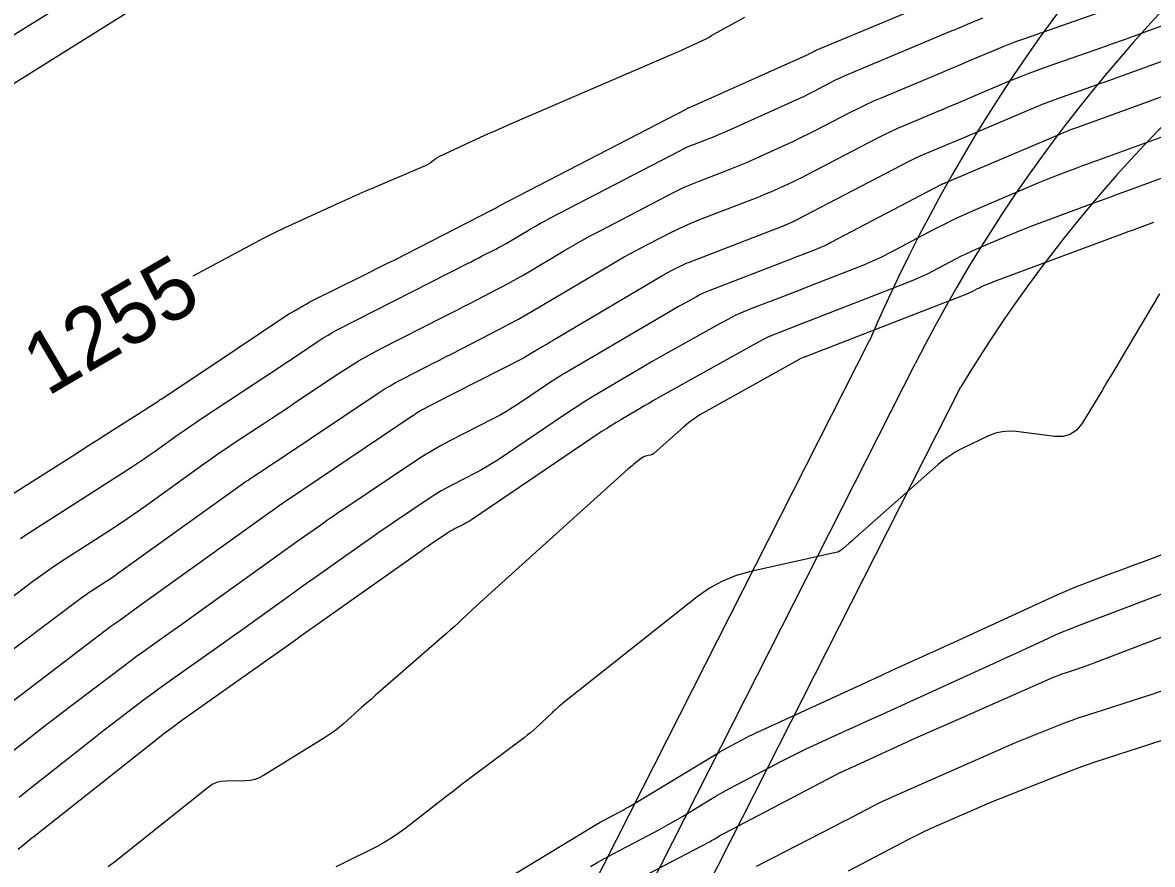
# Model space of a CAD drawing. Extents: x 658976 to 668721, y 639543 to 647196.
# Drawn here: x 662250.4 to 662361, y 642066.5 to 642148.9 of the extents above; entities that cross this region are included whole.
import ezdxf

# ---------------------------------------------------------------- set-up
doc = ezdxf.new("R2010")
doc.units = 0
for name, color, linetype in [('Ex_Contour Labels', 7, 'Continuous'), ('Ex_Major Contours', 7, 'Continuous'), ('Ex_Minor Contours', 7, 'Continuous'), ('R_Water', 7, 'Continuous')]:
    doc.layers.add(name, color=color, linetype=linetype)

msp = doc.modelspace()

# ---------------------------------------------------------------- linework, layer by layer
at = {"layer": 'Ex_Major Contours'}
for points in [[(662260.86, 642150.06), (662245.33, 642140.36)], [(662267.07, 642124.14), (662273.12, 642127.37), (662274.1, 642127.89), (662275.08, 642128.38), (662276.08, 642128.86), (662277.08, 642129.33), (662281.38, 642131.28), (662282.24, 642131.68), (662283.11, 642132.06), (662283.98, 642132.44), (662284.85, 642132.81), (662289.84, 642134.94), (662289.97, 642135), (662290.09, 642135.06), (662290.2, 642135.14), (662290.31, 642135.22), (662290.75, 642135.55), (662290.86, 642135.63), (662290.98, 642135.71), (662291.1, 642135.78), (662291.22, 642135.84), (662295.22, 642137.7), (662295.93, 642138.02), (662296.64, 642138.34), (662297.35, 642138.66), (662298.07, 642138.97), (662314.38, 642146), (662314.69, 642146.13), (662315, 642146.27), (662315.31, 642146.41), (662315.62, 642146.56), (662317.36, 642147.37), (662317.42, 642147.4), (662317.48, 642147.43), (662317.54, 642147.47), (662317.6, 642147.5), (662317.82, 642147.66), (662317.87, 642147.7), (662317.93, 642147.74), (662317.99, 642147.77), (662318.05, 642147.81), (662321.09, 642149.47)], [(662366.24, 642146.7), (662357.08, 642143.37), (662356.45, 642143.14), (662355.83, 642142.92), (662355.2, 642142.7), (662354.58, 642142.48), (662352.07, 642141.6), (662351.45, 642141.38), (662350.83, 642141.15), (662350.21, 642140.9), (662349.6, 642140.65), (662341.54, 642137.23), (662341.17, 642137.08), (662340.81, 642136.93), (662340.44, 642136.77), (662340.08, 642136.62), (662338.61, 642136), (662338.24, 642135.85), (662337.88, 642135.68), (662337.53, 642135.51), (662337.17, 642135.33), (662326.11, 642129.57), (662326, 642129.51), (662325.89, 642129.45), (662325.78, 642129.4), (662325.67, 642129.35), (662325.21, 642129.14), (662325.1, 642129.09), (662324.98, 642129.05), (662324.87, 642129), (662324.75, 642128.95), (662315.53, 642125.41), (662315.31, 642125.32), (662315.09, 642125.22), (662314.87, 642125.12), (662314.66, 642125.02), (662313.81, 642124.58), (662313.6, 642124.46), (662313.39, 642124.35), (662313.18, 642124.23), (662312.98, 642124.11), (662302.27, 642117.77), (662302.03, 642117.62), (662301.79, 642117.48), (662301.55, 642117.34), (662301.31, 642117.2), (662299.93, 642116.39), (662299.9, 642116.37), (662299.86, 642116.34), (662299.82, 642116.32), (662299.78, 642116.3), (662299.64, 642116.2), (662299.6, 642116.17), (662299.56, 642116.15), (662299.53, 642116.13), (662299.49, 642116.11), (662292.59, 642112.59), (662292.27, 642112.43), (662291.96, 642112.27), (662291.65, 642112.11), (662291.34, 642111.95), (662289.49, 642111), (662289.44, 642110.97), (662289.39, 642110.94), (662289.38, 642110.94), (662289.37, 642110.93), (662289.35, 642110.92), (662289.34, 642110.92), (662288.86, 642110.6), (662288.78, 642110.54), (662288.7, 642110.48), (662288.61, 642110.43), (662288.53, 642110.37), (662276.41, 642102.23), (662276.24, 642102.11), (662276.06, 642101.99), (662275.89, 642101.87), (662275.72, 642101.75), (662275.03, 642101.27), (662274.86, 642101.15), (662274.69, 642101.02), (662274.52, 642100.9), (662274.34, 642100.78), (662261.31, 642091.41), (662261.12, 642091.27), (662260.93, 642091.14), (662260.74, 642091), (662260.55, 642090.87), (662259.78, 642090.32), (662259.59, 642090.19), (662259.4, 642090.05), (662259.21, 642089.91), (662259.02, 642089.77), (662247.35, 642080.91)], [(662361.71, 642122.38), (662357.99, 642116.09), (662357.51, 642115.3), (662357.03, 642114.5), (662356.55, 642113.7), (662356.07, 642112.91), (662354.08, 642109.64), (662353.57, 642109.01), (662352.96, 642108.58), (662352.25, 642108.38), (662351.44, 642108.38), (662347.68, 642108.88), (662346.98, 642108.92), (662346.3, 642108.86), (662345.63, 642108.71), (662344.97, 642108.45), (662342.39, 642107.21), (662341.76, 642106.88), (662341.16, 642106.51), (662340.58, 642106.1), (662340.03, 642105.64), (662331.88, 642098.43), (662331.74, 642098.3), (662331.59, 642098.17), (662331.44, 642098.03), (662331.29, 642097.9), (662330.7, 642097.38), (662330.54, 642097.26), (662330.38, 642097.16), (662330.2, 642097.08), (662330.01, 642097.03), (662321.67, 642095.18), (662320.25, 642094.78), (662318.9, 642094.23), (662317.62, 642093.53), (662316.42, 642092.68), (662303.24, 642082.23), (662303.15, 642082.16), (662303.06, 642082.09), (662302.97, 642082.01), (662302.89, 642081.94), (662302.55, 642081.63), (662302.47, 642081.56), (662302.39, 642081.48), (662302.3, 642081.41), (662302.22, 642081.33), (662300.68, 642079.89), (662300.39, 642079.63), (662300.09, 642079.38), (662299.79, 642079.13), (662299.48, 642078.89), (662294.06, 642074.82), (662293.3, 642074.25), (662292.55, 642073.67), (662291.8, 642073.1), (662291.05, 642072.51), (662287.94, 642070.08), (662287.25, 642069.56), (662286.53, 642069.08), (662285.79, 642068.63), (662285.03, 642068.22), (662281.74, 642066.56), (662281.05, 642066.25)], [(662297.66, 642065), (662306.29, 642070.24), (662306.61, 642070.43), (662306.92, 642070.61), (662307.24, 642070.78), (662307.56, 642070.96), (662308.85, 642071.63), (662309.17, 642071.81), (662309.49, 642071.98), (662309.8, 642072.16), (662310.12, 642072.35), (662318.28, 642077.29), (662318.64, 642077.5), (662319, 642077.71), (662319.36, 642077.91), (662319.73, 642078.1), (662321.2, 642078.87), (662321.56, 642079.06), (662321.93, 642079.24), (662322.31, 642079.42), (662322.68, 642079.6), (662332.44, 642084.07), (662333.2, 642084.42), (662333.95, 642084.76), (662334.71, 642085.11), (662335.47, 642085.46), (662338.5, 642086.84), (662339.26, 642087.19), (662340.02, 642087.53), (662340.78, 642087.88), (662341.54, 642088.23), (662350.95, 642092.57), (662351.69, 642092.9), (662352.43, 642093.22), (662353.18, 642093.53), (662353.93, 642093.82), (662356.95, 642094.97), (662357.7, 642095.25), (662358.46, 642095.54), (662359.22, 642095.82), (662359.97, 642096.1), (662372.12, 642100.64)]]:
    msp.add_lwpolyline(points, dxfattribs=at)
at = {"layer": 'Ex_Minor Contours'}
for points in [[(662257.02, 642152.41), (662246.99, 642146.15)], [(662248.38, 642102.12), (662255.23, 642106.47), (662256.08, 642107.02), (662256.93, 642107.56), (662257.78, 642108.1), (662258.63, 642108.65), (662263.7, 642111.89), (662263.72, 642111.9), (662263.74, 642111.92), (662263.76, 642111.93), (662263.78, 642111.94), (662263.85, 642112), (662263.87, 642112.01), (662263.89, 642112.02), (662263.91, 642112.04), (662263.93, 642112.05), (662267.13, 642114.16), (662267.67, 642114.52), (662268.21, 642114.88), (662268.75, 642115.24), (662269.29, 642115.6), (662275.96, 642120.08), (662276.2, 642120.23), (662276.44, 642120.39), (662276.69, 642120.54), (662276.94, 642120.68), (662277.94, 642121.26), (662278.19, 642121.4), (662278.44, 642121.54), (662278.69, 642121.67), (662278.95, 642121.8), (662283.46, 642124.04), (662284.3, 642124.45), (662285.14, 642124.87), (662285.97, 642125.29), (662286.81, 642125.71), (662296.28, 642130.55), (662296.31, 642130.56), (662296.35, 642130.58), (662296.38, 642130.6), (662296.41, 642130.61), (662296.54, 642130.68), (662296.58, 642130.7), (662296.61, 642130.72), (662296.64, 642130.73), (662296.67, 642130.75), (662296.87, 642130.87), (662296.91, 642130.9), (662296.96, 642130.92), (662297, 642130.94), (662297.05, 642130.97), (662315.4, 642140.5), (662315.47, 642140.54), (662315.54, 642140.57), (662315.61, 642140.6), (662315.68, 642140.63), (662315.97, 642140.74), (662316.05, 642140.77), (662316.12, 642140.8), (662316.19, 642140.83), (662316.26, 642140.86), (662327.12, 642145.74), (662327.2, 642145.78), (662327.29, 642145.82), (662327.37, 642145.86), (662327.45, 642145.9), (662327.77, 642146.07), (662327.85, 642146.11), (662327.93, 642146.15), (662328.01, 642146.18), (662328.09, 642146.22), (662342.44, 642152.23)], [(662247.87, 642091.57), (662251.38, 642094.21), (662252.26, 642094.86), (662253.16, 642095.49), (662254.07, 642096.11), (662254.99, 642096.71), (662258.81, 642099.16), (662259.75, 642099.77), (662260.68, 642100.4), (662261.61, 642101.04), (662262.52, 642101.68), (662268.13, 642105.71), (662268.87, 642106.23), (662269.6, 642106.75), (662270.35, 642107.26), (662271.1, 642107.76), (662274.1, 642109.74), (662274.86, 642110.24), (662275.61, 642110.74), (662276.36, 642111.24), (662277.1, 642111.74), (662281.37, 642114.59), (662282.34, 642115.22), (662283.33, 642115.82), (662284.33, 642116.39), (662285.36, 642116.93), (662291.59, 642120.11), (662292.25, 642120.45), (662292.9, 642120.78), (662293.56, 642121.12), (662294.22, 642121.46), (662296.85, 642122.81), (662297.51, 642123.15), (662298.16, 642123.51), (662298.8, 642123.87), (662299.44, 642124.24), (662303.42, 642126.6), (662304.3, 642127.11), (662305.19, 642127.61), (662306.08, 642128.1), (662306.98, 642128.58), (662314.06, 642132.26), (662314.69, 642132.57), (662315.33, 642132.87), (662315.97, 642133.15), (662316.62, 642133.41), (662319.24, 642134.42), (662319.89, 642134.67), (662320.54, 642134.94), (662321.19, 642135.21), (662321.83, 642135.5), (662325.08, 642136.96), (662325.83, 642137.3), (662326.58, 642137.66), (662327.32, 642138.02), (662328.06, 642138.4), (662331.32, 642140.1), (662332.12, 642140.5), (662332.92, 642140.89), (662333.73, 642141.26), (662334.54, 642141.61), (662340.37, 642144.05), (662341.04, 642144.33), (662341.7, 642144.61), (662342.37, 642144.89), (662343.04, 642145.17), (662345.71, 642146.31), (662346.38, 642146.58), (662347.05, 642146.85), (662347.73, 642147.1), (662348.41, 642147.35), (662359.13, 642151.08)], [(662246.81, 642085.59), (662255.95, 642092.47), (662256.26, 642092.7), (662256.58, 642092.92), (662256.9, 642093.14), (662257.22, 642093.35), (662258.53, 642094.19), (662258.85, 642094.4), (662259.18, 642094.61), (662259.49, 642094.83), (662259.81, 642095.06), (662271.91, 642103.75), (662272.18, 642103.94), (662272.45, 642104.13), (662272.73, 642104.31), (662273, 642104.5), (662274.11, 642105.23), (662274.38, 642105.41), (662274.66, 642105.59), (662274.93, 642105.78), (662275.21, 642105.96), (662285.2, 642112.65), (662285.77, 642113.02), (662286.35, 642113.37), (662286.94, 642113.71), (662287.54, 642114.02), (662289.97, 642115.26), (662290.58, 642115.57), (662291.18, 642115.88), (662291.79, 642116.19), (662292.4, 642116.5), (662297.01, 642118.88), (662297.98, 642119.38), (662298.94, 642119.9), (662299.89, 642120.44), (662300.83, 642120.99), (662307.85, 642125.15), (662308.57, 642125.57), (662309.29, 642125.98), (662310.02, 642126.38), (662310.76, 642126.77), (662313.72, 642128.3), (662314.46, 642128.68), (662315.22, 642129.03), (662315.98, 642129.36), (662316.75, 642129.67), (662321.88, 642131.64), (662322.32, 642131.81), (662322.76, 642131.99), (662323.2, 642132.18), (662323.64, 642132.37), (662325.37, 642133.15), (662325.81, 642133.35), (662326.24, 642133.55), (662326.66, 642133.77), (662327.09, 642133.98), (662333.98, 642137.57), (662334.69, 642137.93), (662335.4, 642138.28), (662336.13, 642138.61), (662336.86, 642138.92), (662339.79, 642140.15), (662340.52, 642140.46), (662341.26, 642140.77), (662341.99, 642141.08), (662342.72, 642141.39), (662347.01, 642143.21), (662347.97, 642143.6), (662348.94, 642143.99), (662349.92, 642144.35), (662350.9, 642144.7), (662356.06, 642146.5), (662357.12, 642146.88), (662358.18, 642147.25), (662359.24, 642147.63), (662360.3, 642148.01), (662365.42, 642149.88)], [(662250.15, 642098.41), (662250.6, 642098.7), (662261.05, 642105.39), (662261.63, 642105.77), (662262.21, 642106.16), (662262.78, 642106.56), (662263.35, 642106.96), (662265.61, 642108.58), (662266.18, 642108.98), (662266.75, 642109.38), (662267.32, 642109.77), (662267.9, 642110.16), (662275.63, 642115.26), (662276.09, 642115.57), (662276.56, 642115.88), (662277.02, 642116.19), (662277.48, 642116.5), (662279.33, 642117.73), (662279.8, 642118.04), (662280.28, 642118.33), (662280.76, 642118.6), (662281.25, 642118.86), (662293.93, 642125.33), (662294.28, 642125.5), (662294.63, 642125.68), (662294.97, 642125.86), (662295.32, 642126.04), (662296.7, 642126.75), (662297.04, 642126.93), (662297.38, 642127.11), (662297.72, 642127.3), (662298.06, 642127.5), (662300.15, 642128.74), (662300.61, 642129), (662301.07, 642129.27), (662301.54, 642129.52), (662302.01, 642129.77), (662314.73, 642136.38), (662315.08, 642136.56), (662315.43, 642136.72), (662315.79, 642136.88), (662316.15, 642137.02), (662317.61, 642137.58), (662317.97, 642137.72), (662318.33, 642137.87), (662318.69, 642138.02), (662319.05, 642138.18), (662326.04, 642141.32), (662326.49, 642141.53), (662326.93, 642141.74), (662327.37, 642141.95), (662327.81, 642142.18), (662329.55, 642143.08), (662329.98, 642143.31), (662330.42, 642143.52), (662330.87, 642143.72), (662331.32, 642143.91), (662341.4, 642148.14), (662341.78, 642148.3), (662342.15, 642148.45), (662342.53, 642148.61), (662342.9, 642148.77), (662344.4, 642149.41)], [(662367.49, 642143.68), (662353.67, 642138.65), (662353.57, 642138.62), (662353.48, 642138.58), (662353.38, 642138.55), (662353.28, 642138.51), (662352.9, 642138.38), (662352.8, 642138.35), (662352.71, 642138.31), (662352.61, 642138.27), (662352.52, 642138.23), (662340.45, 642133.12), (662340.41, 642133.1), (662340.38, 642133.09), (662340.37, 642133.09), (662340.36, 642133.08), (662340.35, 642133.08), (662340.35, 642133.07), (662329.53, 642127.38), (662329.18, 642127.2), (662328.84, 642127.04), (662328.49, 642126.89), (662328.13, 642126.74), (662326.7, 642126.19), (662326.34, 642126.05), (662325.98, 642125.91), (662325.63, 642125.77), (662325.27, 642125.63), (662317.66, 642122.69), (662317.31, 642122.55), (662316.96, 642122.39), (662316.61, 642122.22), (662316.28, 642122.04), (662314.94, 642121.3), (662314.6, 642121.11), (662314.27, 642120.92), (662313.94, 642120.73), (662313.61, 642120.53), (662303.84, 642114.8), (662303.21, 642114.43), (662302.59, 642114.04), (662301.97, 642113.65), (662301.36, 642113.24), (662298.94, 642111.6), (662298.32, 642111.2), (662297.7, 642110.82), (662297.06, 642110.45), (662296.42, 642110.11), (662292.21, 642107.97), (662291.3, 642107.48), (662290.41, 642106.97), (662289.53, 642106.44), (662288.67, 642105.88), (662281.91, 642101.34), (662281.32, 642100.94), (662280.73, 642100.54), (662280.14, 642100.13), (662279.56, 642099.72), (662277.23, 642098.07), (662276.65, 642097.66), (662276.07, 642097.25), (662275.49, 642096.83), (662274.91, 642096.42), (662267.5, 642091.09), (662266.91, 642090.67), (662266.31, 642090.24), (662265.72, 642089.82), (662265.12, 642089.4), (662262.73, 642087.71), (662262.14, 642087.28), (662261.54, 642086.85), (662260.96, 642086.42), (662260.37, 642085.98), (662253.98, 642081.13), (662253.36, 642080.65), (662252.74, 642080.17), (662252.12, 642079.69), (662251.51, 642079.21), (662249.05, 642077.27)], [(662364.98, 642138.82), (662355.64, 642135.43), (662355.15, 642135.25), (662354.66, 642135.07), (662354.17, 642134.89), (662353.68, 642134.71), (662351.73, 642133.99), (662351.25, 642133.8), (662350.76, 642133.61), (662350.28, 642133.41), (662349.8, 642133.21), (662343.68, 642130.6), (662342.65, 642130.14), (662341.63, 642129.67), (662340.61, 642129.17), (662339.61, 642128.66), (662335.35, 642126.42), (662334.48, 642125.97), (662333.59, 642125.56), (662332.7, 642125.16), (662331.79, 642124.8), (662327.86, 642123.27), (662327.09, 642122.97), (662326.32, 642122.67), (662325.54, 642122.37), (662324.77, 642122.07), (662321.68, 642120.88), (662320.91, 642120.56), (662320.16, 642120.23), (662319.42, 642119.86), (662318.69, 642119.47), (662314.77, 642117.28), (662313.88, 642116.78), (662312.99, 642116.28), (662312.1, 642115.76), (662311.21, 642115.25), (662307.22, 642112.9), (662306.26, 642112.33), (662305.32, 642111.75), (662304.38, 642111.15), (662303.45, 642110.53), (662296.93, 642106.12), (662296.4, 642105.77), (662295.86, 642105.44), (662295.31, 642105.13), (662294.74, 642104.83), (662292.48, 642103.67), (662291.92, 642103.37), (662291.36, 642103.06), (662290.82, 642102.73), (662290.29, 642102.38), (662286.88, 642100.09), (662286.13, 642099.59), (662285.39, 642099.08), (662284.66, 642098.57), (662283.92, 642098.05), (662278.9, 642094.5), (662278.18, 642093.99), (662277.46, 642093.47), (662276.73, 642092.96), (662276.02, 642092.44), (662273.14, 642090.38), (662272.42, 642089.86), (662271.7, 642089.34), (662270.98, 642088.83), (662270.26, 642088.32), (662265.04, 642084.64), (662264.36, 642084.15), (662263.69, 642083.66), (662263.02, 642083.16), (662262.35, 642082.66), (662259.69, 642080.64), (662259.02, 642080.13), (662258.36, 642079.62), (662257.7, 642079.11), (662257.05, 642078.59), (662250.59, 642073.49), (662250.02, 642073.04)], [(662362.14, 642133.75), (662358.46, 642132.42), (662357.54, 642132.09), (662356.63, 642131.75), (662355.71, 642131.41), (662354.8, 642131.07), (662349.27, 642129.01), (662348.62, 642128.76), (662347.97, 642128.51), (662347.33, 642128.25), (662346.69, 642127.98), (662344.01, 642126.83), (662343.43, 642126.58), (662342.86, 642126.31), (662342.29, 642126.04), (662341.73, 642125.75), (662339.5, 642124.58), (662338.94, 642124.29), (662338.37, 642124.02), (662337.79, 642123.77), (662337.21, 642123.53), (662327.48, 642119.75), (662327.06, 642119.59), (662326.65, 642119.43), (662326.23, 642119.27), (662325.82, 642119.11), (662324.15, 642118.46), (662323.74, 642118.29), (662323.34, 642118.11), (662322.94, 642117.92), (662322.54, 642117.71), (662312.62, 642112.17), (662312.16, 642111.91), (662311.69, 642111.64), (662311.23, 642111.38), (662310.77, 642111.11), (662308.94, 642110.03), (662308.48, 642109.76), (662308.03, 642109.48), (662307.58, 642109.19), (662307.14, 642108.9), (662294.43, 642100.31), (662294.23, 642100.17), (662294.03, 642100.05), (662293.82, 642099.93), (662293.6, 642099.82), (662292.74, 642099.38), (662292.53, 642099.26), (662292.32, 642099.14), (662292.11, 642099.02), (662291.91, 642098.89), (662290.62, 642098.02), (662290.33, 642097.83), (662290.05, 642097.63), (662289.77, 642097.44), (662289.49, 642097.24), (662279.28, 642090.01), (662279.06, 642089.86), (662278.84, 642089.7), (662278.62, 642089.54), (662278.4, 642089.39), (662277.53, 642088.76), (662277.31, 642088.6), (662277.09, 642088.45), (662276.87, 642088.29), (662276.65, 642088.13), (662266.29, 642080.82), (662266.06, 642080.65), (662265.82, 642080.48), (662265.59, 642080.31), (662265.36, 642080.13), (662264.44, 642079.43), (662264.21, 642079.26), (662263.98, 642079.08), (662263.75, 642078.9), (662263.52, 642078.72), (662251.47, 642069.19), (662251.28, 642069.04), (662251.08, 642068.88), (662250.89, 642068.73), (662250.7, 642068.57), (662249.93, 642067.94)], [(662361.12, 642129.35), (662359.44, 642128.74), (662359.01, 642128.58), (662358.59, 642128.43), (662358.17, 642128.27), (662357.75, 642128.12), (662345.44, 642123.53), (662345.31, 642123.47), (662345.17, 642123.42), (662345.03, 642123.37), (662344.9, 642123.31), (662344.34, 642123.07), (662344.22, 642123.02), (662344.1, 642122.96), (662343.98, 642122.9), (662343.86, 642122.84), (662343.39, 642122.59), (662343.27, 642122.53), (662343.15, 642122.48), (662343.03, 642122.43), (662342.91, 642122.38), (662327.1, 642116.23), (662327.04, 642116.21), (662326.98, 642116.19), (662326.92, 642116.16), (662326.86, 642116.14), (662326.63, 642116.05), (662326.57, 642116.03), (662326.51, 642116), (662326.46, 642115.97), (662326.4, 642115.94), (662317.26, 642110.84), (662316.69, 642110.5), (662316.13, 642110.12), (662315.59, 642109.72), (662315.08, 642109.29), (662312.23, 642106.76), (662312.14, 642106.69), (662312.04, 642106.63), (662311.94, 642106.59), (662311.83, 642106.55), (662311.38, 642106.45), (662311.27, 642106.42), (662311.16, 642106.38), (662311.06, 642106.33), (662310.97, 642106.26), (662310.24, 642105.68), (662310.09, 642105.56), (662309.94, 642105.43), (662309.79, 642105.31), (662309.65, 642105.18), (662296.29, 642093.15), (662295.92, 642092.81), (662295.56, 642092.48), (662295.19, 642092.14), (662294.83, 642091.81), (662293.38, 642090.46), (662293.01, 642090.12), (662292.65, 642089.79), (662292.28, 642089.46), (662291.9, 642089.13), (662285.38, 642083.44), (662284.93, 642083.05), (662284.49, 642082.65), (662284.04, 642082.26), (662283.6, 642081.87), (662281.83, 642080.28), (662281.38, 642079.9), (662280.92, 642079.54), (662280.44, 642079.19), (662279.94, 642078.87), (662273.96, 642075.19), (662273.54, 642074.96), (662273.11, 642074.8), (662272.65, 642074.71), (662272.18, 642074.67), (662270.26, 642074.64), (662269.79, 642074.6), (662269.35, 642074.49), (662268.93, 642074.3), (662268.54, 642074.03), (662259.36, 642066.71), (662258.76, 642066.23)], [(662305.99, 642066.29), (662306.7, 642066.71), (662307.42, 642067.11), (662308.15, 642067.49), (662312.3, 642069.68), (662312.98, 642070.04), (662313.65, 642070.41), (662314.32, 642070.79), (662314.98, 642071.18), (662317.6, 642072.77), (662318.26, 642073.16), (662318.93, 642073.55), (662319.6, 642073.92), (662320.28, 642074.28), (662324.75, 642076.62), (662325.53, 642077.02), (662326.32, 642077.41), (662327.11, 642077.79), (662327.9, 642078.16), (662331.09, 642079.62), (662331.89, 642079.98), (662332.68, 642080.35), (662333.48, 642080.71), (662334.28, 642081.08), (662345.43, 642086.16), (662346.11, 642086.47), (662346.79, 642086.78), (662347.46, 642087.09), (662348.14, 642087.4), (662350.84, 642088.65), (662351.52, 642088.96), (662352.21, 642089.25), (662352.9, 642089.53), (662353.59, 642089.8), (662365.56, 642094.34)], [(662306.84, 642063.03), (662317.57, 642068.67), (662317.7, 642068.74), (662317.83, 642068.81), (662317.96, 642068.88), (662318.08, 642068.96), (662318.59, 642069.26), (662318.71, 642069.34), (662318.84, 642069.41), (662318.97, 642069.48), (662319.1, 642069.55), (662330.51, 642075.51), (662330.6, 642075.56), (662330.69, 642075.6), (662330.78, 642075.64), (662330.87, 642075.69), (662331.23, 642075.85), (662331.32, 642075.89), (662331.41, 642075.94), (662331.5, 642075.98), (662331.59, 642076.02), (662336.92, 642078.45), (662337.84, 642078.87), (662338.76, 642079.28), (662339.69, 642079.69), (662340.61, 642080.1), (662351.03, 642084.69), (662351.15, 642084.74), (662351.27, 642084.79), (662351.39, 642084.84), (662351.51, 642084.89), (662351.99, 642085.08), (662352.11, 642085.13), (662352.24, 642085.17), (662352.36, 642085.21), (662352.48, 642085.25), (662353.68, 642085.64), (662353.92, 642085.72), (662354.16, 642085.8), (662354.39, 642085.89), (662354.63, 642085.98), (662374.02, 642093.39)], [(662322.24, 642066.32), (662322.69, 642066.54), (662329.73, 642070.16), (662330.23, 642070.42), (662330.72, 642070.67), (662331.22, 642070.93), (662331.71, 642071.19), (662333.68, 642072.21), (662334.18, 642072.47), (662334.68, 642072.71), (662335.18, 642072.95), (662335.69, 642073.18), (662346.64, 642078), (662347.29, 642078.28), (662347.93, 642078.55), (662348.58, 642078.82), (662349.24, 642079.09), (662351.85, 642080.13), (662352.5, 642080.38), (662353.16, 642080.62), (662353.83, 642080.86), (662354.49, 642081.08), (662360.98, 642083.17), (662362.28, 642083.6)], [(662331.23, 642065.86), (662337.14, 642068.94), (662337.87, 642069.31), (662338.6, 642069.67), (662339.34, 642070.02), (662340.09, 642070.36), (662343.09, 642071.68), (662343.84, 642072), (662344.59, 642072.32), (662345.35, 642072.64), (662346.11, 642072.94), (662351.7, 642075.17), (662352.89, 642075.63), (662354.09, 642076.08), (662355.29, 642076.5), (662356.51, 642076.9), (662372.67, 642082.11)]]:
    msp.add_lwpolyline(points, dxfattribs=at)
at = {"layer": 'R_Water'}
for p, q in [((662216.73, 641887.88), (662333.31, 642117.78)), ((662221.19, 641885.62), (662337.77, 642115.51)), ((662225.65, 641883.36), (662342.23, 642113.25))]:
    msp.add_line(p, q, dxfattribs=at)
for centre, radius, start, end in [((662480.69, 642054.64), 160.33, 105.2469, 156.8108), ((662471.55, 642047.67), 150, 101.5452, 153.1092), ((662462.41, 642040.7), 140.38, 97.3166, 148.8806)]:
    msp.add_arc(centre, radius, start, end, dxfattribs=at)

# ---------------------------------------------------------------- texts
at = {"layer": 'Ex_Contour Labels'}
msp.add_text('1255', height=6, rotation=30.4506, dxfattribs=at).set_placement((662252.79, 642112.27))

doc.saveas('drawing.dxf')
